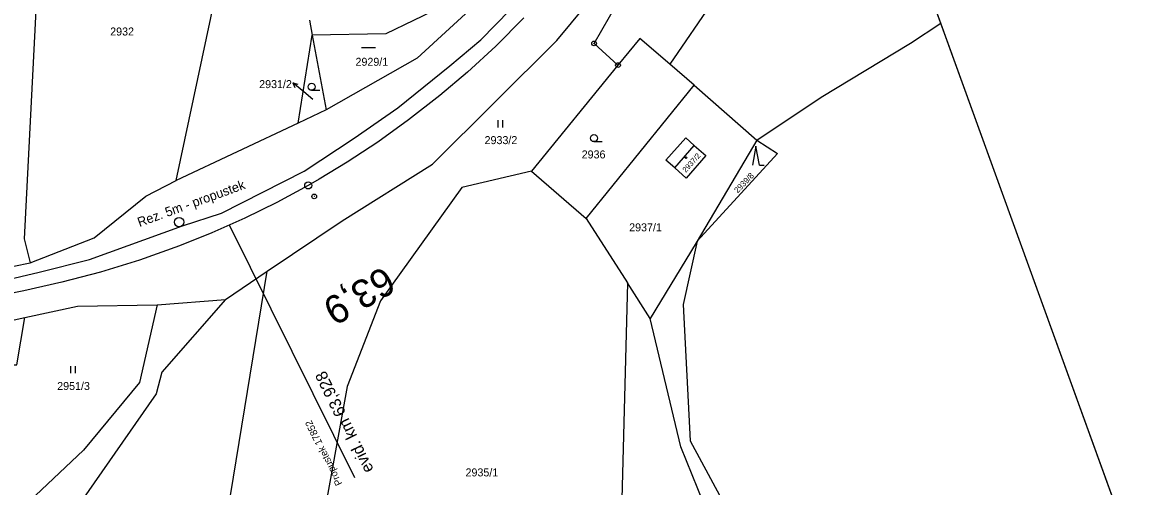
# Model space of a CAD drawing. Extents: x -620552 to -620056, y -1123312 to -1122890.
# Drawn here: x -620295.9 to -620056.1, y -1123143.8 to -1123045.1 of the extents above; entities that cross this region are included whole.
import ezdxf

# ---------------------------------------------------------------- set-up
doc = ezdxf.new("R2010")
doc.units = 0
for name, color, linetype in [('HranDP', 7, 'Continuous'), ('Hranice parcel', 7, 'Continuous'), ('Parcelní čísla', 7, 'Continuous'), ('Pop  PČ popisy', 7, 'Continuous'), ('Rámečky', 7, 'Continuous'), ('Rámečky-tisk', 7, 'Continuous'), ('Vnitřní kresba', 7, 'Continuous'), ('Vrstva 1', 7, 'Continuous'), ('Vrstva 13', 7, 'Continuous'), ('Vrstva 19', 7, 'Continuous'), ('Vrstva 3', 7, 'Continuous'), ('Vrstva 7', 7, 'Continuous'), ('Značky bodu BP', 7, 'Continuous'), ('Značky budov', 7, 'Continuous'), ('Značky kultur', 7, 'Continuous')]:
    doc.layers.add(name, color=color, linetype=linetype)

msp = doc.modelspace()

# ---------------------------------------------------------------- linework, layer by layer
at = {"layer": 'HranDP'}
for p, q in [((-620231.41, -1123063.68), (-620237.39, -1123066.51)), ((-620237.39, -1123066.51), (-620263.28, -1123078.74)), ((-620306.69, -1123098.69), (-620294.3, -1123096.22)), ((-620252.85, -1123104.02), (-620243.96, -1123098.03)), ((-620267.31, -1123105.13), (-620252.85, -1123104.02)), ((-620301.93, -1123109.26), (-620295.45, -1123107.86))]:
    msp.add_line(p, q, dxfattribs=at)
for points in [[(-620243.96, -1123098.03), (-620228.02, -1123087.3), (-620208.81, -1123075.27), (-620182.41, -1123048.95), (-620179.31, -1123045.19), (-620168.12, -1123031.65)], [(-620197.49, -1123039.27), (-620212.08, -1123052.71), (-620231.41, -1123063.68)], [(-620294.3, -1123096.22), (-620280.71, -1123090.89), (-620269.72, -1123082.03), (-620263.28, -1123078.74)], [(-620295.45, -1123107.86), (-620284.26, -1123105.43), (-620267.31, -1123105.13)]]:
    msp.add_lwpolyline(points, dxfattribs=at)
at = {"layer": 'Hranice parcel'}
for p, q in [((-620263.28, -1123078.74), (-620242.46, -1122980.18)), ((-620148.96, -1123040.16), (-620158.39, -1123054.01)), ((-620234.98, -1123044.6), (-620234.38, -1123047.81)), ((-620237.39, -1123066.51), (-620234.38, -1123047.81)), ((-620234.38, -1123047.81), (-620231.41, -1123063.68)), ((-620169.42, -1123054.19), (-620187.77, -1123076.72)), ((-620153.24, -1123058.46), (-620158.39, -1123054.01)), ((-620176.15, -1123086.79), (-620153.24, -1123058.46)), ((-620153.24, -1123058.46), (-620139.89, -1123070.16)), ((-620231.41, -1123063.68), (-620237.39, -1123066.51)), ((-620237.39, -1123066.51), (-620263.28, -1123078.74)), ((-620139.89, -1123070.16), (-620152.59, -1123091.6)), ((-620187.77, -1123076.72), (-620176.15, -1123086.79)), ((-620176.15, -1123086.79), (-620167.39, -1123100.52)), ((-620152.8, -1123091.95), (-620162.55, -1123108.1)), ((-620152.59, -1123091.6), (-620152.8, -1123091.95)), ((-620306.69, -1123098.69), (-620294.3, -1123096.22)), ((-620258.49, -1123186.41), (-620243.96, -1123098.03)), ((-620252.85, -1123104.02), (-620243.96, -1123098.03)), ((-620167.39, -1123100.52), (-620169.58, -1123182.3)), ((-620162.55, -1123108.1), (-620167.39, -1123100.52)), ((-620267.31, -1123105.13), (-620252.85, -1123104.02)), ((-620301.93, -1123109.26), (-620295.45, -1123107.86))]:
    msp.add_line(p, q, dxfattribs=at)
for points in [[(-620289.02, -1123011.5), (-620293.05, -1123041.17), (-620295.61, -1123091.1), (-620294.3, -1123096.22)], [(-620169.42, -1123054.19), (-620174.5, -1123049.57), (-620168, -1123038.2), (-620152.59, -1123026.13)], [(-620243.96, -1123098.03), (-620228.02, -1123087.3), (-620208.81, -1123075.27), (-620182.41, -1123048.95), (-620179.31, -1123045.19), (-620168.12, -1123031.65)], [(-620197.49, -1123039.27), (-620207, -1123041.9), (-620218.72, -1123047.54), (-620234.38, -1123047.81)], [(-620197.49, -1123039.27), (-620212.08, -1123052.71), (-620231.41, -1123063.68)], [(-620139.89, -1123070.16), (-620126.22, -1123060.97), (-620107.28, -1123049.5), (-620100.81, -1123045.29)], [(-620158.39, -1123054.01), (-620164.78, -1123048.5), (-620169.42, -1123054.19)], [(-620159.28, -1123074.39), (-620154.99, -1123069.68), (-620153.24, -1123071.27), (-620150.78, -1123073.44), (-620154.95, -1123078.2), (-620157.37, -1123076.03), (-620159.28, -1123074.39)], [(-620139.89, -1123070.16), (-620135.5, -1123072.99), (-620152.59, -1123091.6)], [(-620187.77, -1123076.72), (-620202.59, -1123080.2), (-620219.89, -1123104.3), (-620226.94, -1123122.55), (-620232.45, -1123152.64), (-620233.85, -1123191.46)], [(-620294.3, -1123096.22), (-620280.71, -1123090.89), (-620269.72, -1123082.03), (-620263.28, -1123078.74)], [(-620152.59, -1123091.6), (-620155.57, -1123105.08), (-620154.07, -1123134.06), (-620143.02, -1123154.56), (-620138.08, -1123176.89), (-620193.14, -1123193.74), (-620221.59, -1123191.7), (-620233.71, -1123192.88), (-620259.81, -1123191.23)], [(-620267.31, -1123105.13), (-620271.09, -1123121.69), (-620283, -1123136.04), (-620303.5, -1123155.32)], [(-620295.45, -1123107.86), (-620284.26, -1123105.43), (-620267.31, -1123105.13)], [(-620252.85, -1123104.02), (-620266.37, -1123119.45), (-620267.54, -1123124.06), (-620286.24, -1123150.98), (-620288.99, -1123164.76), (-620262.29, -1123185.63)], [(-620298.49, -1123117.9), (-620297.19, -1123117.91), (-620295.45, -1123107.86)], [(-620169.58, -1123182.3), (-620139.22, -1123177.02), (-620156.05, -1123135.37), (-620162.55, -1123108.1)]]:
    msp.add_lwpolyline(points, dxfattribs=at)
at = {"layer": 'Pop  PČ popisy'}
for p, q in [((-620236.21, -1123059.88), (-620238.51, -1123057.95)), ((-620238.51, -1123057.95), (-620237.42, -1123058.21)), ((-620238.51, -1123057.95), (-620238.06, -1123058.98)), ((-620234.25, -1123061.52), (-620236.21, -1123059.88))]:
    msp.add_line(p, q, dxfattribs=at)
at = {"layer": 'Rámečky'}
msp.add_line((-620056.07, -1123168.86), (-620157.19, -1122889.6), dxfattribs=at)
at = {"layer": 'Rámečky-tisk'}
msp.add_lwpolyline([(-620450.98, -1123311.85), (-620056.07, -1123168.86), (-620157.19, -1122889.6), (-620552.1, -1123032.6)], dxfattribs=at)
at = {"layer": 'Vnitřní kresba'}
msp.add_line((-620157.37, -1123076.03), (-620153.24, -1123071.27), dxfattribs=at)
at = {"layer": 'Vrstva 1'}
for points in [[(-620302.99, -1123100.7), (-620292.4, -1123098.24), (-620281.7, -1123095.56), (-620261.93, -1123088.35), (-620253.64, -1123085.66), (-620236.13, -1123076.73), (-620225.47, -1123069.74), (-620216.19, -1123063.28), (-620205.15, -1123054.34), (-620198.59, -1123048.78), (-620192.32, -1123042.45), (-620189.21, -1123039.13), (-620192.93, -1123035.47), (-620189.24, -1123032.05), (-620184.32, -1123027.49), (-620172.92, -1123014.85), (-620170.12, -1123011.86), (-620165.72, -1123007.16), (-620158.18, -1122991.64), (-620154.53, -1122984.74), (-620154, -1122982.93), (-620152.3, -1122977.09), (-620150.63, -1122971.37)], [(-620189.42, -1123044.16), (-620195.41, -1123050.18), (-620201.42, -1123055.71), (-620207.3, -1123060.67), (-620213.93, -1123065.85), (-620220.45, -1123070.54), (-620226.96, -1123074.82), (-620232.91, -1123078.44), (-620235.25, -1123079.78), (-620241.89, -1123083.37), (-620248.71, -1123086.73), (-620255.76, -1123089.87), (-620262.62, -1123092.63), (-620271.12, -1123095.65), (-620279.4, -1123098.2), (-620287.58, -1123100.35), (-620295.67, -1123102.19), (-620303.02, -1123103.7)]]:
    msp.add_lwpolyline(points, dxfattribs=at)
at = {"layer": 'Vrstva 13'}
msp.add_circle((-620262.69, -1123087.56), 1, dxfattribs=at)
at = {"layer": 'Vrstva 19'}
msp.add_line((-620225.37, -1123141.98), (-620251.96, -1123088.19), dxfattribs=at)
at = {"layer": 'Vrstva 7'}
msp.add_line((-620233.94, -1123082.09), (-620234.03, -1123082.14), dxfattribs=at)
for centre, radius in [((-620235.25, -1123079.78), 0.75), ((-620233.98, -1123082.12), 0.5)]:
    msp.add_circle(centre, radius, dxfattribs=at)
at = {"layer": 'Značky bodu BP'}
for centre, radius in [((-620174.5, -1123049.57), 0.5), ((-620174.5, -1123049.57), 0.0303), ((-620169.42, -1123054.19), 0.5), ((-620169.42, -1123054.19), 0.0303)]:
    msp.add_circle(centre, radius, dxfattribs=at)
at = {"layer": 'Značky budov'}
msp.add_circle((-620154.96, -1123073.88), 0.175, dxfattribs=at)
at = {"layer": 'Značky kultur'}
for p, q in [((-620223.92, -1123050.46), (-620220.92, -1123050.46)), ((-620234.53, -1123059.54), (-620232.78, -1123059.54)), ((-620194.87, -1123067.42), (-620194.87, -1123065.92)), ((-620193.87, -1123067.42), (-620193.87, -1123065.92)), ((-620174.52, -1123070.46), (-620172.77, -1123070.46)), ((-620140.1, -1123071.45), (-620140.85, -1123075.45)), ((-620139.35, -1123075.45), (-620140.1, -1123071.45)), ((-620139.35, -1123075.45), (-620138.35, -1123075.45)), ((-620285.7, -1123119.71), (-620285.7, -1123118.21)), ((-620284.7, -1123119.71), (-620284.7, -1123118.21))]:
    msp.add_line(p, q, dxfattribs=at)
for centre in [(-620234.53, -1123058.79), (-620174.52, -1123069.71)]:
    msp.add_circle(centre, 0.75, dxfattribs=at)

# ---------------------------------------------------------------- texts
at = {"layer": 'Parcelní čísla'}
for s, p in [('2932', (-620277.33, -1123047.89)), ('2929/1', (-620225.2, -1123054.33)), ('2931/2', (-620245.67, -1123059.08)), ('2933/2', (-620197.77, -1123070.99)), ('2936', (-620177.14, -1123074.03)), ('2937/1', (-620167.05, -1123089.54)), ('2951/3', (-620288.59, -1123123.28)), ('2935/1', (-620201.82, -1123141.65))]:
    msp.add_text(s, height=1.7, dxfattribs=at).set_placement(p)
for s, height, rotation, p in [('2937/2', 1.139, 48, (-620155, -1123077.11)), ('2939/8', 1.254, 46, (-620143.98, -1123081.5))]:
    msp.add_text(s, height=height, rotation=rotation, dxfattribs=at).set_placement(p)
at = {"layer": 'Vrstva 19'}
for s, height, p in [('evid. km 63,928', 2.5, (-620221.28, -1123140.2)), ('Propustek 17852', 1.5, (-620227.97, -1123143.18))]:
    msp.add_text(s, height=height, rotation=116.0458, dxfattribs=at).set_placement(p)
at = {"layer": 'Vrstva 3'}
msp.add_text('Rez. 5m - propustek', height=2, rotation=19.9058, dxfattribs=at).set_placement((-620271.1, -1123088.62))
at = {"layer": 'Vrstva 7'}
msp.add_text('63,9', height=6, rotation=209.9159, dxfattribs=at).set_placement((-620219.08, -1123096.76))

doc.saveas('drawing.dxf')
